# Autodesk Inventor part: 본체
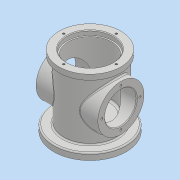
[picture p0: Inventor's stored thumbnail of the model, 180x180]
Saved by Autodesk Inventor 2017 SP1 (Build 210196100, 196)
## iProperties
Part Number: 본체
Material: 일반
Document SubType Name: Modeling
Designer: MRC
Density: 1 g/cm^3
Appearance: 기본값
Author: MRC
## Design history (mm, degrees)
sketch "스케치1"
  geometry: C1 r 40 at (0, 0); 1 further point
  constraints: 1 centre point, 1 coincident
  dimensions: "d0" = 80 diameter of C1
extrude "돌출1" new body sketch "스케치1" distance "d1" = 88; taper "d2" = 0 deg
sketch "스케치2"
  geometry: C1 r 55 at (0, 0); 1 further point
  constraints: 1 centre point, 1 coincident
  dimensions: "d3" = 110 diameter of C1
extrude "돌출2" join sketch "스케치2" distance "d4" = 10; taper "d5" = 0 deg
sketch "스케치5"
  geometry: C1 r 47 at (0, 0); 1 further point
  constraints: 1 centre point, 1 coincident
  dimensions: "d18" = 94 diameter of C1
extrude "돌출4" join sketch "스케치5" distance "d19" = 10; taper "d20" = 0 deg
hole "구멍2" diameter "d23" = 66; stored, may be unused: countersink angle "d27" = 90 deg, drill point angle "d29" = 0 deg; dims "d21" = 10, "d22" = 10, "d24" = 6, "d25" = 70, "d26" = 7, "d28" = 86
hole "구멍3" diameter "d32" = 10; stored, may be unused: countersink angle "d36" = 90 deg, drill point angle "d38" = 0 deg; dims "d30" = 10, "d31" = 10, "d33" = 6, "d34" = 66, "d35" = 16, "d37" = 86
node "작업 평면1"
sketch "스케치8"
  geometry: L1 (-55, -10)-(55, -10) reference; C1 r 35 at (0, 44); 1 further point
  constraints: 1 centre point, 1 vertical alignment
  dimensions: "d43" = 70 diameter of C1; "d44" = 54 distance from line of C1.centre L1
extrude "돌출5" join sketch "스케치8" stored distance "d45" = 94; taper "d46" = 0 deg
sketch "스케치9"
  geometry: C1 r 35 at (0, 0) reference; C2 r 24 at (0, 0); 1 further point
  constraints: 1 centre point, 1 coincident
  dimensions: "d47" = 48 diameter of C2
extrude "돌출6" cut sketch "스케치9" stored distance "d48" = 94; taper "d49" = 0 deg
sketch "스케치10"
  geometry: C1 r 24 at (0, 0) reference; 2 further points
  constraints: 1 vertical alignment
  dimensions: "d50" = 29 distance of point (0, -29) C1.centre
hole "구멍4" sketch "스케치10" at (0, -29) diameter "d51" = 3.242; stored, may be unused: countersink angle "d55" = 90 deg, drill point angle "d57" = 118 deg; dims "d52" = 6, "d53" = 12.24, "d54" = 3.58, "d56" = 8
node "작업 평면2"
sketch "스케치11"
  geometry: L1 (0, 57)-(0, 31); L2 (-7, 57)-(-7, 31); L3 (7, 31)-(7, 57); L4 (-55, -10)-(55, -10) reference; A1 r 7 centre (0, 57) between (7, 57) and (-7, 57); A2 r 7 centre (0, 31) between (-7, 31) and (7, 31); 2 further points
  constraints: 8 end point, 4 point on circle, 4 tangent, 2 centre point, 1 midpoint, 1 parallel, 1 vertical, 1 vertical alignment
  dimensions: "d62" = 40 dimension on A2 A1; "d63" = 54 distance from line of point (0, 44) L4; "d77" = 7 radius of A1
extrude "돌출7" join sketch "스케치11" stored distance "d64" = 94; taper "d65" = 15 deg
sketch "스케치12"
  geometry: L1 (7, -57)-(7, -31) reference; L2 (-7, -31)-(-7, -57) reference; A1 r 7 centre (0, -31) between (7, -31) and (-7, -31) reference; A2 r 7 centre (0, -57) between (-7, -57) and (7, -57) reference; 3 further points
  constraints: 2 coincident
hole "구멍5" sketch "스케치12" at (0, -57), (0, -31) diameter "d66" = 4.134; stored, may be unused: countersink angle "d70" = 90 deg, drill point angle "d72" = 118 deg; dims "d67" = 6, "d68" = 12.24, "d69" = 3.58, "d71" = 8
sketch "스케치13"
  geometry: C1 r 50 at (0, 0); 1 further point
  constraints: 1 centre point, 1 coincident, 1 other
  dimensions: "d73" = 100 diameter of C1
feature "엠보싱1" sketch "스케치13" dims "d74" = 0.5, "d75" = 0
fillet "모깎기1" dims "d76" = 2
sketch "스케치14"
  geometry: 2 further points
  constraints: 1 vertical alignment
  dimensions: "d78" = 40 distance of point (0, -40) point (0, 0)
hole "구멍6" sketch "스케치14" at (0, -40) diameter "d79" = 3.242; stored, may be unused: countersink angle "d83" = 90 deg, drill point angle "d85" = 118 deg; dims "d80" = 6, "d81" = 12.24, "d82" = 3.58, "d84" = 8
chamfer "모따기1" distance "d89" = 1; stored, may be unused: second distance "d90" = 2, angle "d91" = 45 deg
fillet "모깎기2" dims "d95" = 3
node "솔리드1"
pattern_circular "원형 패턴1" dims angle "d59" = 360 deg
mirror "미러1"
pattern_circular "원형 패턴2" dims angle "d87" = 360 deg
node "투영된 루프1"
node "투영된 루프2"
other parameters: "d42" = 47, "d61" = 55
